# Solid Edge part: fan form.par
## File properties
Author: Julian Frimmel
Template: Iso Metric Part.par
Last saved by: Julian Frimmel
Revision: 7
Application: Solid Edge
Genauigkeit: 0,990
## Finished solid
Body 1: solid body, 118 faces, 275 edges, 148 vertices.
  Faces by surface: cylinder 42, blend 32, plane 28, torus 12, spline 4
  Edges by curve: circle 107, line 104, intersection 40, curve on surface 16, ellipse 8
Bounding box of the edges (mm; curved faces can reach further): 92.000 x 92.000 x 25.000, from (-46, -46, 0) to (46, 46, 25).
Cylindrical faces by radius (mm): R1 x8, R1.5 x1, R2.165 x8, R5 x20, R45 x1, R46 x4
Toroidal faces (ring radius, tube radius in mm): R6 r1 x4, R40 r5 x4, R56 r10 x4
Planar faces by outward normal: +x 2, +y 2, +z 7, -x 2, -y 2, -z 5, oblique 8
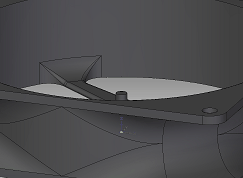
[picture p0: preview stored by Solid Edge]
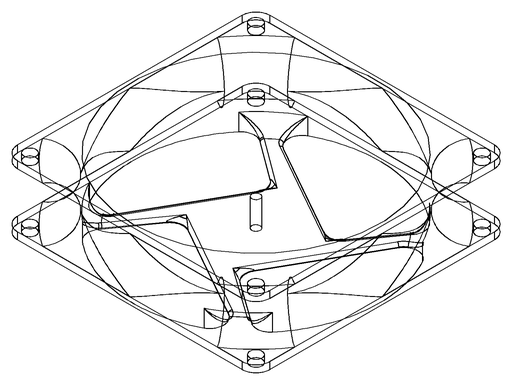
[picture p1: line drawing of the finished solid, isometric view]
